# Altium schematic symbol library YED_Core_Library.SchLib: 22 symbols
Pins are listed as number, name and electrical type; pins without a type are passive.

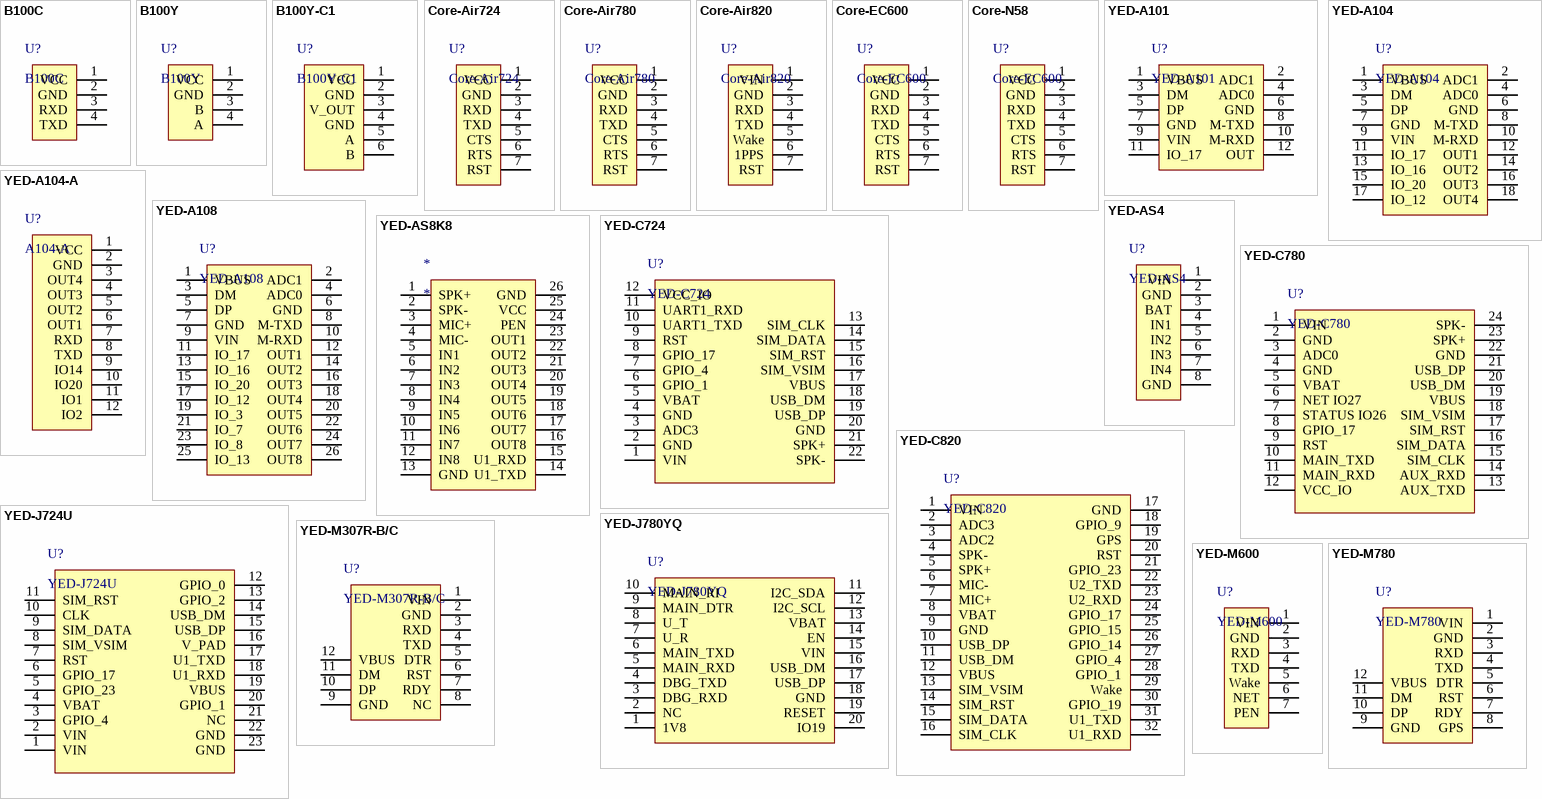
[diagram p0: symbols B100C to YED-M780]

## B100C
designator U?
footprint B100Y/C
pins: 1 VCC, 2 GND, 3 RXD, 4 TXD

## B100Y
designator U?
footprint B100Y/C
pins: 1 VCC, 2 GND, 3 B, 4 A

## B100Y-C1
designator U?
footprint B100Y-C1
pins: 1 VCC, 2 GND, 3 V_OUT, 4 GND, 5 A, 6 B

## Core-Air724
designator U?
footprint Core-Air724
pins: 1 VCC, 2 GND, 3 RXD, 4 TXD, 5 CTS, 6 RTS, 7 RST

## Core-Air780
designator U?
footprint YED-C780
footprint Core-Air780
pins: 1 VCC, 2 GND, 3 RXD, 4 TXD, 5 CTS, 6 RTS, 7 RST

## Core-Air820
designator U?
footprint Core-Air820
pins: 1 VIN, 2 GND, 3 RXD, 4 TXD, 5 Wake, 6 1PPS, 7 RST

## Core-EC600
designator U?
footprint Core-EC600
pins: 1 VCC, 2 GND, 3 RXD, 4 TXD, 5 CTS, 6 RTS, 7 RST

## Core-N58
designator U?, comment Core-EC600
footprint Core-EC600
pins: 1 VCC, 2 GND, 3 RXD, 4 TXD, 5 CTS, 6 RTS, 7 RST

## YED-A101
designator U?
footprint YED-A101
pins: 1 VBUS, 2 ADC1, 3 DM, 4 ADC0, 5 DP, 6 GND, 7 GND, 8 M-TXD, 9 VIN, 10 M-RXD, 11 IO_17, 12 OUT

## YED-A104
designator U?
footprint YED-A104
pins: 1 VBUS, 2 ADC1, 3 DM, 4 ADC0, 5 DP, 6 GND, 7 GND, 8 M-TXD, 9 VIN, 10 M-RXD, 11 IO_17, 12 OUT1, 13 IO_16, 14 OUT2, 15 IO_20, 16 OUT3, 17 IO_12, 18 OUT4

## YED-A104-A
designator U?, comment A104-A
footprint YED-A104-A
pins: 1 VCC, 2 GND, 3 OUT4, 4 OUT3, 5 OUT2, 6 OUT1, 7 RXD, 8 TXD, 9 IO14, 10 IO20, 11 IO1, 12 IO2

## YED-A108
designator U?
footprint YED-A108
pins: 1 VBUS, 2 ADC1, 3 DM, 4 ADC0, 5 DP, 6 GND, 7 GND, 8 M-TXD, 9 VIN, 10 M-RXD, 11 IO_17, 12 OUT1, 13 IO_16, 14 OUT2, 15 IO_20, 16 OUT3, 17 IO_12, 18 OUT4, 19 IO_3, 20 OUT5, 21 IO_7, 22 OUT6, 23 IO_8, 24 OUT7, 25 IO_13, 26 OUT8

## YED-AS4
designator U?
footprint YED-AS4
pins: 1 VIN, 2 GND, 3 BAT, 4 IN1, 5 IN2, 6 IN3, 7 IN4, 8 GND

## YED-AS8K8
designator *
footprint YED-AS8K8
pins: 1 SPK+, 2 SPK-, 3 MIC+, 4 MIC-, 5 IN1, 6 IN2, 7 IN3, 8 IN4, 9 IN5, 10 IN6, 11 IN7, 12 IN8, 13 GND, 14 U1_TXD, 15 U1_RXD, 16 OUT8, 17 OUT7, 18 OUT6, 19 OUT5, 20 OUT4, 21 OUT3, 22 OUT2, 23 OUT1, 24 PEN, 25 VCC, 26 GND

## YED-C724
designator U?
物料厂家: 银尔达电子; 物料类型: 4G模组
footprint YED-C724
pins: 1 VIN, 2 GND, 3 ADC3, 4 GND, 5 VBAT, 6 GPIO_1, 7 GPIO_4, 8 GPIO_17, 9 RST, 10 UART1_TXD, 11 UART1_RXD, 12 VCC_IO, 13 SIM_CLK, 14 SIM_DATA, 15 SIM_RST, 16 SIM_VSIM, 17 VBUS, 18 USB_DM, 19 USB_DP, 20 GND, 21 SPK+, 22 SPK-

## YED-C780
designator U?
物料厂家: 银尔达电子; 物料类型: 4G模组
footprint YED-C780
pins: 1 VIN, 2 GND, 3 ADC0, 4 GND, 5 VBAT, 6 NET IO27, 7 STATUS IO26, 8 GPIO_17, 9 RST, 10 MAIN_TXD, 11 MAIN_RXD, 12 VCC_IO, 13 AUX_TXD, 14 AUX_RXD, 15 SIM_CLK, 16 SIM_DATA, 17 SIM_RST, 18 SIM_VSIM, 19 VBUS, 20 USB_DM, 21 USB_DP, 22 GND, 23 SPK+, 24 SPK-

## YED-C820
designator U?
物料厂家: 银尔达电子; 物料类型: 4G模组
footprint YED-C820
pins: 1 VIN, 2 ADC3, 3 ADC2, 4 SPK-, 5 SPK+, 6 MIC-, 7 MIC+, 8 VBAT, 9 GND, 10 USB_DP, 11 USB_DM, 12 VBUS, 13 SIM_VSIM, 14 SIM_RST, 15 SIM_DATA, 16 SIM_CLK, 17 GND, 18 GPIO_9, 19 GPS, 20 RST, 21 GPIO_23, 22 U2_TXD, 23 U2_RXD, 24 GPIO_17, 25 GPIO_15, 26 GPIO_14, 27 GPIO_4, 28 GPIO_1, 29 Wake, 30 GPIO_19, 31 U1_TXD, 32 U1_RXD

## YED-J724U
designator U?
footprint YED-J724U
pins: 1 VIN, 2 VIN, 3 GPIO_4, 4 VBAT, 5 GPIO_23, 6 GPIO_17, 7 RST, 8 SIM_VSIM, 9 SIM_DATA, 10 CLK, 11 SIM_RST, 12 GPIO_0, 13 GPIO_2, 14 USB_DM, 15 USB_DP, 16 V_PAD, 17 U1_TXD, 18 U1_RXD, 19 VBUS, 20 GPIO_1, 21 NC, 22 GND, 23 GND

## YED-J780YQ
designator U?
footprint YED-J780YQ
pins: 1 1V8, 2 NC, 3 DBG_RXD, 4 DBG_TXD, 5 MAIN_RXD, 6 MAIN_TXD, 7 U_R, 8 U_T, 9 MAIN_DTR, 10 MAIN_RI, 11 I2C_SDA, 12 I2C_SCL, 13 VBAT, 14 EN, 15 VIN, 16 USB_DM, 17 USB_DP, 18 GND, 19 RESET, 20 IO19

## YED-M307R-B/C
designator U?
footprint YED-M780
pins: 1 VIN, 2 GND, 3 RXD, 4 TXD, 5 DTR, 6 RST, 7 RDY, 8 NC, 9 GND, 10 DP, 11 DM, 12 VBUS

## YED-M600
designator U?
footprint YED-M600
pins: 1 VIN, 2 GND, 3 RXD, 4 TXD, 5 Wake, 6 NET, 7 PEN

## YED-M780
designator U?
footprint YED-M780/307R
pins: 1 VIN, 2 GND, 3 RXD, 4 TXD, 5 DTR, 6 RST, 7 RDY, 8 GPS, 9 GND, 10 DP, 11 DM, 12 VBUS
